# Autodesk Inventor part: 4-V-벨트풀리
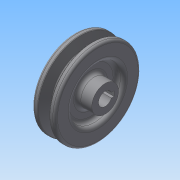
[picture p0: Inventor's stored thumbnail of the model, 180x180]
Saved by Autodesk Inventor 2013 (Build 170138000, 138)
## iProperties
Created: 2015-02
Part Number: 4-V-벨트풀리
Material: 일반
Document SubType Name: Modeling
Designer: Administrator
Density: 1 g/cm^3
Author: Administrator
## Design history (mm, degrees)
sketch "스케치1"
  geometry: L1 (0, 0)-(25, 0); L2 (0, 11)-(6, 11); L3 (6, 11)-(6, 21.5); L4 (6, 21.5)-(0, 21.5); L5 (0, 21.5)-(0, 35.2); L6 (0, 35.2)-(4.675, 35.2); L7 (4.675, 35.2)-(7.426, 26.2); L8 (7.426, 26.2)-(11.574, 26.2); L9 (11.574, 26.2)-(14.325, 35.2); L10 (14.325, 35.2)-(19, 35.2); L11 (19, 35.2)-(19, 21.5); L12 (19, 21.5)-(13, 21.5); L13 (13, 21.5)-(13, 11); L14 (25, 5.5)-(0, 5.5); L15 (0, 11)-(0, 5.5); L16 (25, 5.5)-(25, 11); L17 (25, 11)-(13, 11); 2 further points
  constraints: 34 end point, 7 parallel, 4 collinear, 4 perpendicular, 3 equal length, 2 point on line, 2 vertical alignment, 1 horizontal, 1 horizontal alignment, 1 vertical
  dimensions: "d1" = 25 distance of L1.start L1.end; "d3" = 11 diameter of L14 L1; "d7" = 19 distance between parallel lines of L5 L11; "d8" = 43 diameter of L4 L1; "d9" = 8 distance of point (5.5, 32.5) point (13.5, 32.5); "d11" = 34 deg angle of L7 L9; "d13" = 2.7 vertical distance of point (13.5, 32.5) L9.end; "d14" = 6.3 vertical distance of L8.end point (13.5, 32.5); "d15" = 65 diameter of point (5.5, 32.5) L1; "d16" = 22 diameter of L17 L1; "d17" = 6 distance of L11.end L12.end; "d18" = 6 distance of L3.end L4.end
revolve "회전1" sketch "스케치1" stored, may be unused: angle "d19" = 90 deg
sketch "스케치2"
  geometry: L1 (-2, 5.123)-(-2, 7.3); L2 (-2, 7.3)-(2, 7.3); L3 (2, 7.3)-(2, 5.123); A1 r 5.5 centre (0, 0) between (-2, 5.123) and (2, 5.123) reference; 1 further point
  constraints: 6 end point, 2 point on circle, 1 midpoint, 1 parallel, 1 perpendicular, 1 vertical, 1 vertical alignment
  dimensions: "d20" = 4 distance of L1.end L2.end; "d22" = 12.8 dimension on A1 L2
extrude "돌출1" cut sketch "스케치2" stored distance "d23" = 10; taper "d24" = 0 deg
fillet "모깎기1" dims "d25" = 1, "d26" = 0.5, "d27" = 2, "d28" = 3
fillet "모깎기2" dims "d29" = 3
node "솔리드1"
